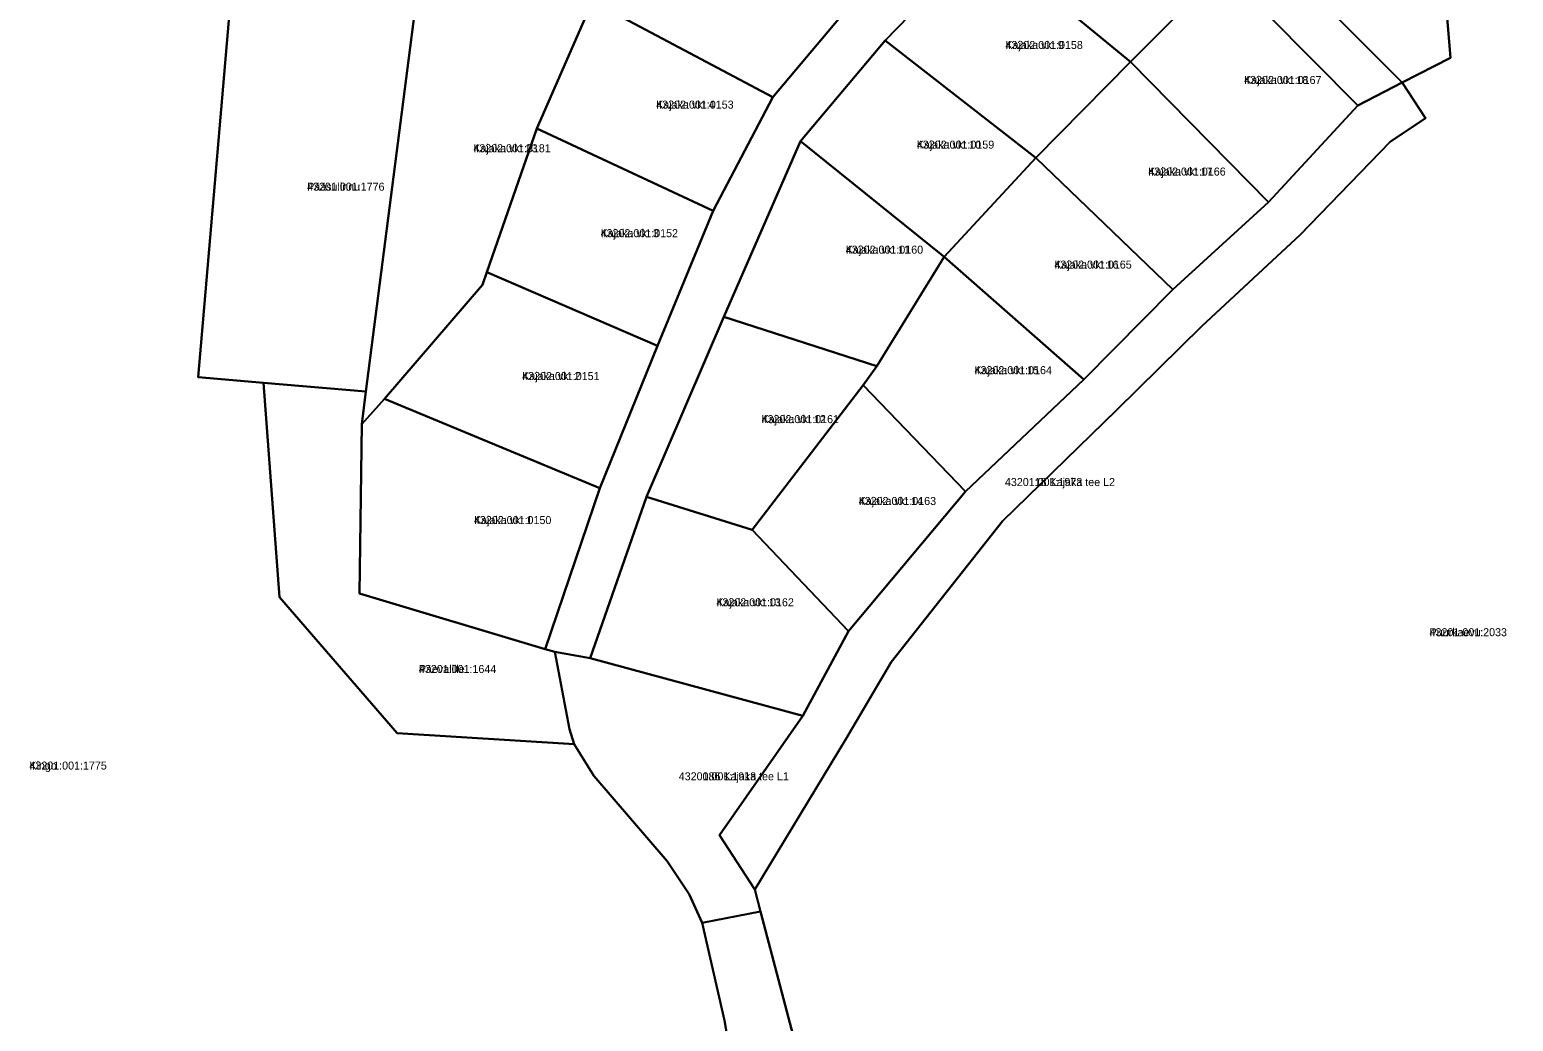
# Model space of a CAD drawing. Extents: x 661852 to 683758, y 6469495 to 6482657.
# Drawn here: x 665529.2 to 665807.3, y 6471028.1 to 6471214 of the extents above; entities that cross this region are included whole.
import ezdxf

# ---------------------------------------------------------------- set-up
doc = ezdxf.new("R2010")
doc.units = 0
for name, color, linetype in [('L_AADRESS', 7, 'Continuous'), ('PIIR', 7, 'Continuous'), ('TUNNUS', 7, 'Continuous')]:
    doc.layers.add(name, color=color, linetype=linetype)

msp = doc.modelspace()

# ---------------------------------------------------------------- linework, layer by layer
at = {"layer": 'PIIR'}
for points in [[(665714.3, 6471269.45), (665733.93, 6471252.93), (665753.87, 6471236.65), (665786.46, 6471204.1), (665778.11, 6471199.83), (665752.84, 6471225.36), (665722.84, 6471250.36), (665707.76, 6471230.82), (665689.55, 6471212), (665673.66, 6471193.13), (665659.29, 6471160.21), (665644.8, 6471126.48), (665634.26, 6471096.23), (665627.62, 6471097.4), (665625.85, 6471097.9), (665636.04, 6471128.1), (665646.89, 6471154.75), (665657.32, 6471180.05), (665668.49, 6471201.39), (665683.13, 6471218.76), (665700.9, 6471236.46), (665716.59, 6471255.2), (665688.21, 6471279.09), (665694.47, 6471286.2)], [(665795.48, 6471208.75), (665786.46, 6471204.1), (665753.87, 6471236.65), (665775.91, 6471264.46), (665784.52, 6471257.54), (665791.48, 6471257.24)], [(665673.21, 6471021.95), (665666.19, 6471048.71), (665665.1, 6471052.86), (665682.16, 6471081.03), (665690.7, 6471095.45), (665711.53, 6471121.88), (665732.89, 6471142.71), (665748.91, 6471158.46), (665767.33, 6471175.55), (665784.18, 6471192.99), (665790.82, 6471197.44), (665786.46, 6471204.1), (665795.48, 6471208.75), (665791.48, 6471257.24), (665822.01, 6471246.94), (665857.96, 6471249.95), (665886.27, 6471252.42), (665904.61, 6471135.01), (665918.06, 6471004.84), (665868.57, 6471000.65), (665770.3, 6470992.05), (665738.2, 6470995.8), (665701.71, 6471016.32), (665681.89, 6471021.95)], [(665735.52, 6471208), (665707.76, 6471230.82), (665722.84, 6471250.36), (665752.84, 6471225.36)], [(665668.49, 6471201.39), (665636.32, 6471218.41), (665655.39, 6471241.21), (665683.13, 6471218.76)], [(665717.76, 6471190), (665689.55, 6471212), (665707.76, 6471230.82), (665735.52, 6471208)], [(665778.11, 6471199.83), (665761.41, 6471181.69), (665735.52, 6471208), (665752.84, 6471225.36)], [(665592.93, 6471219.62), (665601.59, 6471218.91), (665592.24, 6471146.2), (665573.04, 6471147.84), (665560.82, 6471148.88), (665567.02, 6471221.71)], [(665601.59, 6471218.91), (665617.37, 6471217.4), (665633.26, 6471216.06), (665624.29, 6471195.51), (665614.87, 6471168.6), (665614.07, 6471166.22), (665595.71, 6471144.81), (665591.46, 6471140.08), (665592.24, 6471146.2)], [(665624.29, 6471195.51), (665633.26, 6471216.06), (665636.32, 6471218.41), (665668.49, 6471201.39), (665657.32, 6471180.05)], [(665700.59, 6471171.45), (665673.66, 6471193.13), (665689.55, 6471212), (665717.76, 6471190)], [(665743.45, 6471165.35), (665717.76, 6471190), (665735.52, 6471208), (665761.41, 6471181.69)], [(665658.5, 6471063.01), (665674.1, 6471085.4), (665682.66, 6471101.27), (665704.58, 6471127.44), (665726.81, 6471148.48), (665743.45, 6471165.35), (665761.41, 6471181.69), (665778.11, 6471199.83), (665786.46, 6471204.1), (665790.82, 6471197.44), (665784.18, 6471192.99), (665767.33, 6471175.55), (665748.91, 6471158.46), (665732.89, 6471142.71), (665711.53, 6471121.88), (665690.7, 6471095.45), (665682.16, 6471081.03), (665665.1, 6471052.86)], [(665614.87, 6471168.6), (665624.29, 6471195.51), (665657.32, 6471180.05), (665646.89, 6471154.75)], [(665687.98, 6471150.95), (665659.29, 6471160.21), (665673.66, 6471193.13), (665700.59, 6471171.45)], [(665726.81, 6471148.48), (665700.59, 6471171.45), (665717.76, 6471190), (665743.45, 6471165.35)], [(665704.58, 6471127.44), (665685.43, 6471147.4), (665687.98, 6471150.95), (665700.59, 6471171.45), (665726.81, 6471148.48)], [(665614.87, 6471168.6), (665646.89, 6471154.75), (665636.04, 6471128.1), (665595.71, 6471144.81), (665614.07, 6471166.22)], [(665685.43, 6471147.4), (665664.59, 6471120.27), (665644.8, 6471126.48), (665659.29, 6471160.21), (665687.98, 6471150.95)], [(665573.04, 6471147.84), (665592.24, 6471146.2), (665591.46, 6471140.08), (665591, 6471108.31), (665625.85, 6471097.9), (665627.62, 6471097.4), (665630.41, 6471082.93), (665631.29, 6471080.1), (665598.09, 6471082.14), (665576.04, 6471107.64)], [(665704.58, 6471127.44), (665682.66, 6471101.27), (665664.59, 6471120.27), (665685.43, 6471147.4)], [(665591, 6471108.31), (665591.46, 6471140.08), (665595.71, 6471144.81), (665636.04, 6471128.1), (665625.85, 6471097.9)], [(665682.66, 6471101.27), (665674.1, 6471085.4), (665634.26, 6471096.23), (665644.8, 6471126.48), (665664.59, 6471120.27)], [(665627.62, 6471097.4), (665634.26, 6471096.23), (665674.1, 6471085.4), (665658.5, 6471063.01), (665665.1, 6471052.86), (665666.19, 6471048.71), (665655.26, 6471046.63), (665652.79, 6471052), (665648.7, 6471058.19), (665634.97, 6471074.14), (665631.29, 6471080.1), (665630.41, 6471082.93)]]:
    msp.add_lwpolyline(points, close=True, dxfattribs=at)
for points in [[(665567.02, 6471221.71), (665560.82, 6471148.88), (665573.04, 6471147.84), (665576.04, 6471107.64), (665598.09, 6471082.14), (665631.29, 6471080.1), (665634.97, 6471074.14), (665648.7, 6471058.19), (665652.79, 6471052), (665655.26, 6471046.63), (665659.41, 6471028.29), (665662.28, 6471011.74)], [(665662.28, 6471011.74), (665659.41, 6471028.29), (665655.26, 6471046.63), (665666.19, 6471048.71), (665673.21, 6471021.95)]]:
    msp.add_lwpolyline(points, dxfattribs=at)

# ---------------------------------------------------------------- texts
at = {"layer": 'L_AADRESS'}
for s, p in [('Kajaka vkt 9', (665712.09, 6471210.41)), ('Kajaka vkt 18', (665756.82, 6471203.85)), ('Kajaka vkt 4', (665646.64, 6471199.23)), ('Kajaka vkt 23', (665612.36, 6471191.05)), ('Kajaka vkt 10', (665695.48, 6471191.73)), ('Kajaka vkt 17', (665738.86, 6471186.68)), ('Pääsulinnu', (665581.21, 6471183.85)), ('Kajaka vkt 3', (665636.22, 6471175.13)), ('Kajaka vkt 11', (665682.16, 6471172.04)), ('Kajaka vkt 16', (665721.25, 6471169.24)), ('Kajaka vkt 15', (665706.3, 6471149.45)), ('Kajaka vkt 2', (665621.52, 6471148.35)), ('Kajaka vkt 12', (665666.39, 6471140.27)), ('4320118 Kajaka tee L2', (665711.99, 6471128.48)), ('Kajaka vkt 14', (665684.59, 6471124.93)), ('Kajaka vkt 1', (665612.48, 6471121.35)), ('Kajaka vkt 13', (665657.93, 6471105.94)), ('Puurkaevu', (665791.58, 6471100.33)), ('Päevalille', (665602.16, 6471093.43)), ('Kingo', (665529.16, 6471075.33)), ('4320086 Kajaka tee L1', (665650.86, 6471073.32))]:
    msp.add_text(s, height=1.5, dxfattribs=at).set_placement(p)
at = {"layer": 'TUNNUS'}
for s, p in [('43202:001:0158', (665712.09, 6471210.41)), ('43202:001:0167', (665756.82, 6471203.85)), ('43202:001:0153', (665646.64, 6471199.23)), ('43202:001:0181', (665612.36, 6471191.05)), ('43202:001:0159', (665695.48, 6471191.73)), ('43202:001:0166', (665738.86, 6471186.68)), ('43201:001:1776', (665581.21, 6471183.85)), ('43202:001:0152', (665636.22, 6471175.13)), ('43202:001:0160', (665682.16, 6471172.04)), ('43202:001:0165', (665721.25, 6471169.24)), ('43202:001:0164', (665706.3, 6471149.45)), ('43202:001:0151', (665621.52, 6471148.35)), ('43202:001:0161', (665666.39, 6471140.27)), ('43201:001:1973', (665711.99, 6471128.48)), ('43202:001:0163', (665684.59, 6471124.93)), ('43202:001:0150', (665612.48, 6471121.35)), ('43202:001:0162', (665657.93, 6471105.94)), ('43201:001:2033', (665791.58, 6471100.33)), ('43201:001:1644', (665602.16, 6471093.43)), ('43201:001:1775', (665529.16, 6471075.33)), ('43201:001:1918', (665650.86, 6471073.32))]:
    msp.add_text(s, height=1.5, dxfattribs=at).set_placement(p)

doc.saveas('drawing.dxf')
